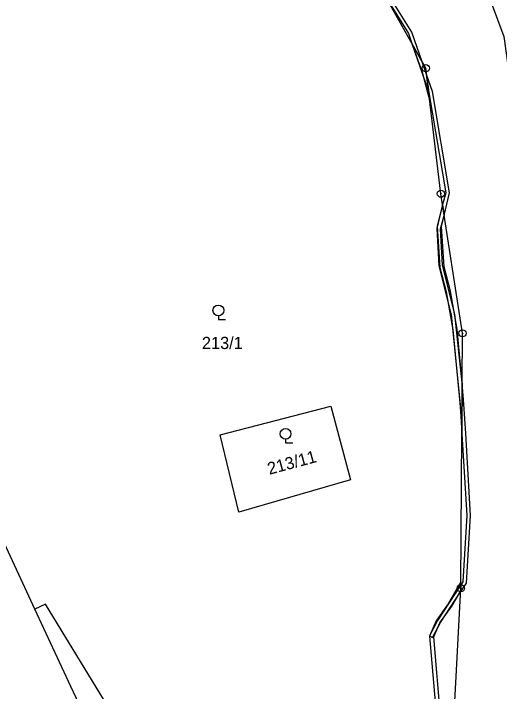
# Model space of a CAD drawing. Extents: x -779723 to -777378, y -1011169 to -1009297.
# Drawn here: x -779012.9 to -778945.2, y -1010301.7 to -1010207.4 of the extents above; entities that cross this region are included whole.
import ezdxf

# ---------------------------------------------------------------- set-up
doc = ezdxf.new("R2010")
doc.units = 0
for name, color, linetype in [('Hranice parcel', 7, 'Continuous'), ('Parcelní čísla', 7, 'Continuous'), ('Věcná břemena k části', 7, 'Continuous'), ('Značky bodu BP', 7, 'Continuous'), ('Značky kultur', 7, 'Continuous')]:
    doc.layers.add(name, color=color, linetype=linetype)

msp = doc.modelspace()

# ---------------------------------------------------------------- linework, layer by layer
at = {"layer": 'Hranice parcel'}
msp.add_line((-779009.89, -1010290.29), (-779014.69, -1010279.95), dxfattribs=at)
for points in [[(-778970.48, -1010181.53), (-778969.19, -1010181.68), (-778956.78, -1010189.07), (-778948.1, -1010201.08), (-778944.59, -1010210.6), (-778941.69, -1010231.16)], [(-778951.52, -1010304.9), (-778950.58, -1010287.37), (-778950.58, -1010286.9), (-778950.34, -1010251.89), (-778953.35, -1010232.46), (-778955.45, -1010215), (-778962.68, -1010202.09), (-778972.6, -1010193.75), (-778987.54, -1010189.4), (-778999.84, -1010191.68), (-779009.45, -1010195.21), (-779017.34, -1010206.13), (-779023.92, -1010222.47), (-779024.96, -1010244.9), (-779026.78, -1010253.95)], [(-778965.93, -1010272.29), (-778981.47, -1010276.78), (-778984.11, -1010266.01), (-778968.66, -1010262.03), (-778965.93, -1010272.29)], [(-779037.1, -1010298.8), (-779036.94, -1010319.12), (-779030.77, -1010318.99), (-779025.76, -1010314.84), (-779021.61, -1010311.89), (-779003.74, -1010303.52), (-779004.9, -1010301.02), (-779009.89, -1010290.29)], [(-778994.79, -1010311.83), (-779008.43, -1010289.59), (-779009.89, -1010290.29)]]:
    msp.add_lwpolyline(points, dxfattribs=at)
at = {"layer": 'Věcná břemena k části'}
for points in [[(-778957.38, -1010211.55), (-778955.96, -1010214.09), (-778957.39, -1010209.96), (-778960.42, -1010205.12), (-778961.57, -1010204.08), (-778960.8, -1010205.44), (-778957.85, -1010210.18)], [(-778955.04, -1010218.38), (-778955.35, -1010215.86), (-778955.96, -1010214.09), (-778957.38, -1010211.55)], [(-778954.87, -1010219.79), (-778955.45, -1010215), (-778957.38, -1010211.55), (-778955.95, -1010215.54)], [(-778952.88, -1010235.5), (-778952.14, -1010232.36), (-778954.52, -1010218.25), (-778955.35, -1010215.86), (-778955.04, -1010218.38), (-778952.66, -1010232.34), (-778953.11, -1010233.98)], [(-778950.44, -1010265.88), (-778950.39, -1010258.76), (-778951.42, -1010249.23), (-778953.15, -1010242.4), (-778953.43, -1010237.36), (-778952.88, -1010235.5), (-778953.11, -1010233.98), (-778953.93, -1010237.32), (-778953.65, -1010242.48), (-778951.91, -1010249.31), (-778950.68, -1010261.8)], [(-778950.43, -1010265.29), (-778950.39, -1010258.76), (-778951.08, -1010251.32), (-778952.03, -1010246.01), (-778952.92, -1010242.63), (-778953.26, -1010237.02), (-778952.88, -1010235.5), (-778953.11, -1010233.98), (-778953.86, -1010236.96), (-778953.52, -1010242.73), (-778952.61, -1010246.13), (-778951.68, -1010251.4), (-778950.73, -1010261.57)], [(-778950.44, -1010265.88), (-778949.73, -1010277.24), (-778950.31, -1010286.49), (-778950.58, -1010286.9), (-778950.58, -1010287.37), (-778950.61, -1010287.87), (-778949.81, -1010286.65), (-778949.23, -1010277.24), (-778949.88, -1010265.84), (-778950.18, -1010261.76), (-778950.39, -1010258.76), (-778950.43, -1010265.29)], [(-778950.6, -1010287.72), (-778950.57, -1010286.48), (-778952.33, -1010289.54), (-778954.01, -1010291.89), (-778954.95, -1010294.05), (-778953.94, -1010305.88), (-778951.76, -1010309.46), (-778951.7, -1010308.5), (-778953.36, -1010305.72), (-778954.33, -1010294.15), (-778953.49, -1010292.19), (-778951.83, -1010289.86)], [(-778950.58, -1010287.37), (-778950.58, -1010286.9), (-778953.83, -1010291.87), (-778954.96, -1010293.98), (-778954.52, -1010294.22), (-778953.39, -1010292.13), (-778950.61, -1010287.87), (-778950.6, -1010287.72)]]:
    msp.add_lwpolyline(points, close=True, dxfattribs=at)
at = {"layer": 'Značky bodu BP'}
for centre, radius in [((-778955.45, -1010215), 0.5), ((-778955.45, -1010215), 0.0303), ((-778953.35, -1010232.46), 0.5), ((-778953.35, -1010232.46), 0.0303), ((-778950.34, -1010251.89), 0.5), ((-778950.34, -1010251.89), 0.0303), ((-778950.58, -1010287.37), 0.5), ((-778950.58, -1010287.37), 0.0303)]:
    msp.add_circle(centre, radius, dxfattribs=at)
at = {"layer": 'Značky kultur'}
for p, q in [((-778984.34, -1010249.452), (-778984.34, -1010249.95)), ((-778984.34, -1010249.95), (-778983.339, -1010249.95)), ((-778974.98, -1010266.632), (-778974.98, -1010267.13)), ((-778974.98, -1010267.13), (-778973.979, -1010267.13))]:
    msp.add_line(p, q, dxfattribs=at)
for centre in [(-778984.339, -1010248.701), (-778974.979, -1010265.881)]:
    msp.add_circle(centre, 0.75, dxfattribs=at)

# ---------------------------------------------------------------- texts
at = {"layer": 'Parcelní čísla'}
msp.add_text('213/1', height=1.7, dxfattribs=at).set_placement((-778986.63, -1010254.08))
msp.add_text('213/11', height=1.7, rotation=15, dxfattribs=at).set_placement((-778977.253, -1010271.586))

doc.saveas('drawing.dxf')
